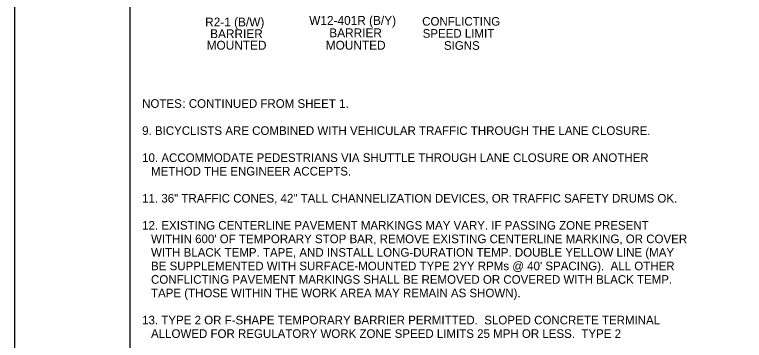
# Model space of a CAD drawing. Extents: x 99982 to 100176, y 99905 to 100011.
# Drawn here: x 100019.06 to 100025, y 99912.89 to 99915.53 of the extents above; entities that cross this region are included whole.
import ezdxf

# ---------------------------------------------------------------- set-up
doc = ezdxf.new("R2010")
doc.units = 0
for name, color, linetype in [('SH_GI_GeneralNotesBodyText', 7, 'Continuous'), ('SH_GI_PlotLimits', 7, 'Continuous'), ('SH_GI_SheetBorder', 7, 'Continuous'), ('TR_SN_ConstructionSigns', 7, 'Continuous')]:
    doc.layers.add(name, color=color, linetype=linetype)

msp = doc.modelspace()

# ---------------------------------------------------------------- linework, layer by layer
at = {"layer": 'SH_GI_PlotLimits'}
msp.add_lwpolyline([(100019.0625, 99909.6875), (100036.0625, 99909.6875), (100036.0625, 99920.6875), (100019.0625, 99920.6875)], close=True, dxfattribs=at)
at = {"layer": 'SH_GI_SheetBorder'}
msp.add_line((100020, 99920.375), (100020, 99910), dxfattribs=at)

# ---------------------------------------------------------------- texts
at = {"layer": 'SH_GI_GeneralNotesBodyText'}
for s, p in [('NOTES', (100020.1, 99914.778)), (': CONTINUED FROM SHEET 1.', (100020.4275, 99914.778)), ('9. BICYCLISTS ARE COMBINED WITH VEHICULAR TRAFFIC THROUGH THE LANE CLOSURE.', (100020.1, 99914.5582)), ('10. ACCOMMODATE PEDESTRIANS VIA SHUTTLE THROUGH LANE CLOSURE OR ANOTHER ', (100020.1, 99914.3384)), ('METHOD THE ENGINEER ACCEPTS.', (100020.1722, 99914.2285)), ('11. 36" TRAFFIC CONES, 42" TALL CHANNELIZATION DEVICES, OR TRAFFIC SAFETY DRUMS OK.', (100020.1, 99914.0087)), ('12. EXISTING CENTERLINE PAVEMENT MARKINGS MAY VARY. IF PASSING ZONE PRESENT ', (100020.1, 99913.7889)), ("WITHIN 600' OF TEMPORARY STOP BAR, REMOVE EXISTING CENTERLINE MARKING, OR COVER ", (100020.1722, 99913.679)), ('WITH BLACK TEMP. TAPE, AND INSTALL LONG-DURATION TEMP. DOUBLE YELLOW LINE (MAY ', (100020.1722, 99913.5691)), ("BE SUPPLEMENTED WITH SURFACE-MOUNTED TYPE 2YY RPMs @ 40' SPACING).  ALL OTHER ", (100020.1722, 99913.4592)), ('CONFLICTING PAVEMENT MARKINGS SHALL BE REMOVED OR COVERED WITH BLACK TEMP. ', (100020.1722, 99913.3493)), ('TAPE (THOSE WITHIN THE WORK AREA MAY REMAIN AS SHOWN).', (100020.1722, 99913.2394)), ('13. TYPE 2 OR F-SHAPE TEMPORARY BARRIER PERMITTED.  SLOPED CONCRETE TERMINAL ', (100020.1, 99913.0196)), ('ALLOWED FOR REGULATORY WORK ZONE SPEED LIMITS 25 MPH OR LESS.  TYPE 2 ', (100020.1722, 99912.9097))]:
    msp.add_text(s, height=0.07, rotation=360, dxfattribs=at).set_placement(p)
at = {"layer": 'TR_SN_ConstructionSigns'}
for s, p in [('W12-401R (B/Y)', (100021.4589, 99915.4518)), ('R2-1 (B/W)', (100020.6124, 99915.439)), ('BARRIER', (100020.6533, 99915.3439)), ('BARRIER', (100021.6221, 99915.351)), ('MOUNTED', (100020.6247, 99915.2502)), ('MOUNTED', (100021.5935, 99915.2502))]:
    msp.add_text(s, height=0.072, rotation=360, dxfattribs=at).set_placement(p)
for s, p in [('CONFLICTING', (100022.3778, 99915.4452)), ('SPEED LIMIT', (100022.3816, 99915.3472)), ('SIGNS', (100022.5546, 99915.2492))]:
    msp.add_text(s, height=0.07, dxfattribs=at).set_placement(p)

doc.saveas('drawing.dxf')
